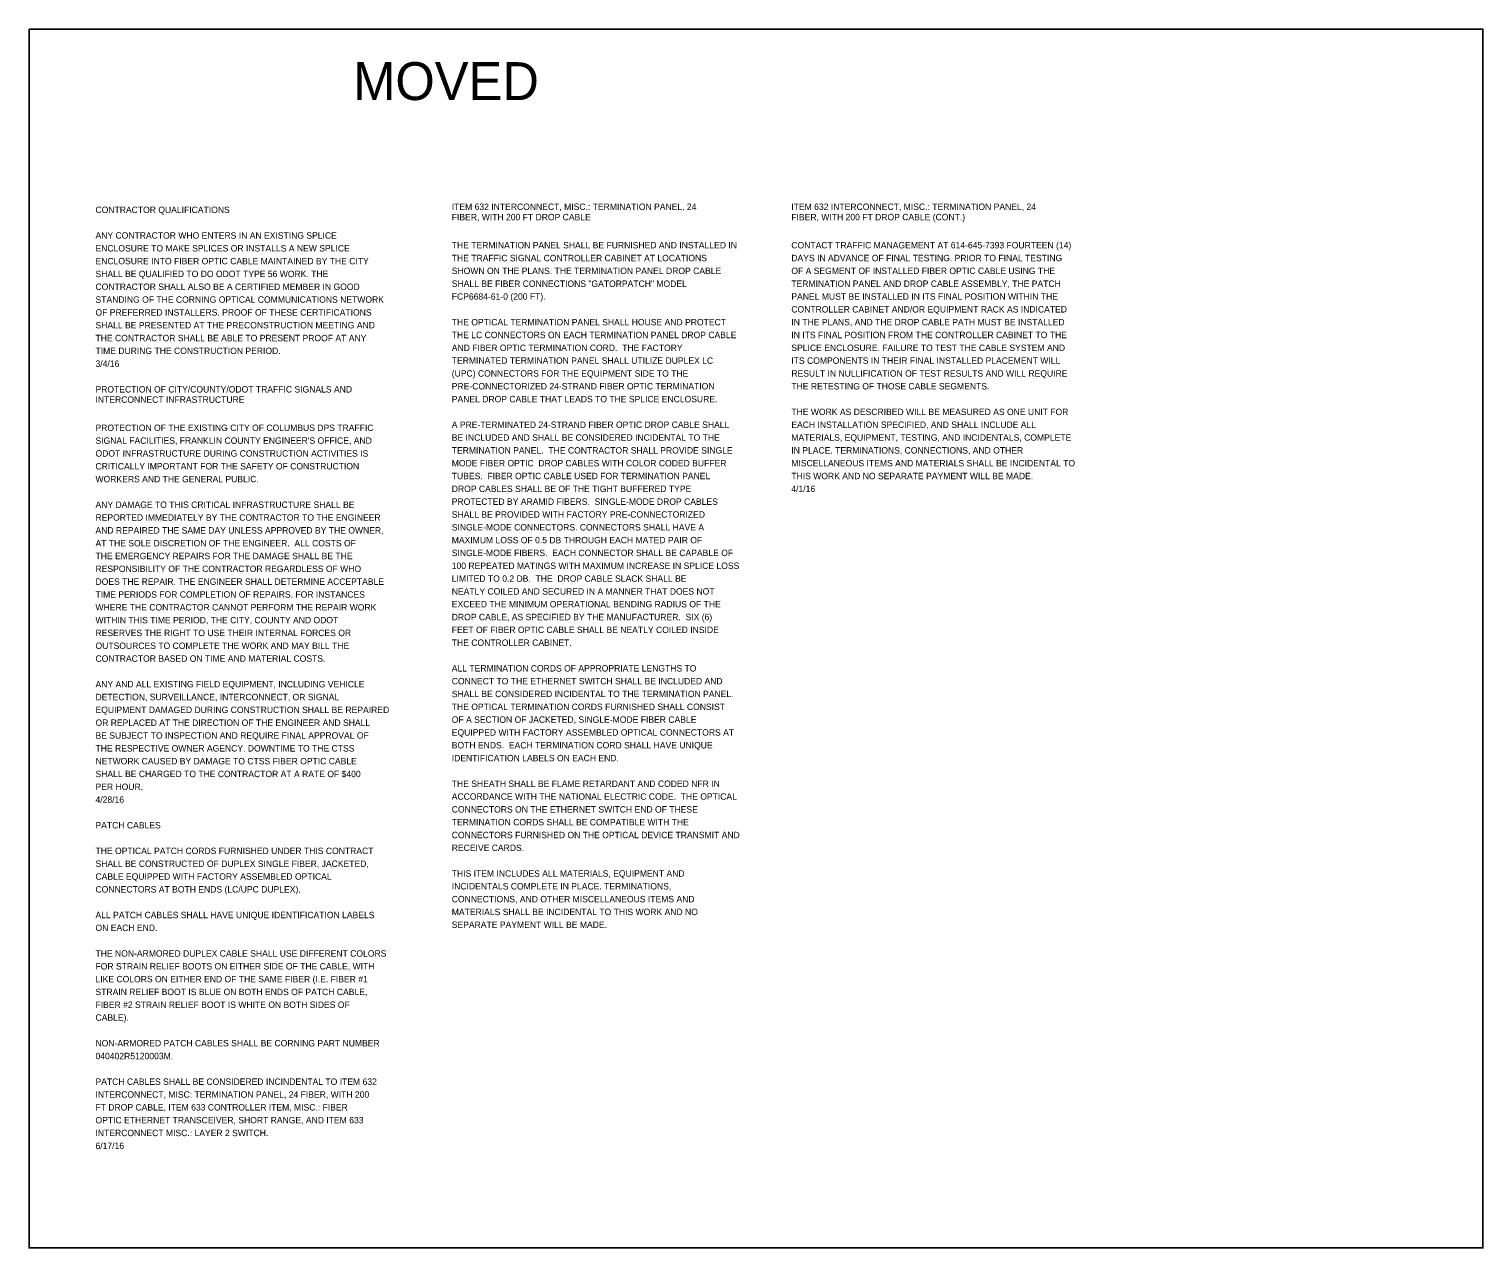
# Model space of a CAD drawing. Extents: x -38 to 65, y -51 to 25.
# Drawn here: x -38.27 to -6.5, y -10.91 to 15.7 of the extents above; entities that cross this region are included whole.
import ezdxf

# ---------------------------------------------------------------- set-up
doc = ezdxf.new("R2010")
doc.units = 0
doc.layers.add('SH_Data', color=7, linetype='Continuous')
doc.layers.add('SH_Text', color=7, linetype='Continuous')

msp = doc.modelspace()

# ---------------------------------------------------------------- linework, layer by layer
at = {"layer": 'SH_Text'}
msp.add_lwpolyline([(-38.266, 15.704), (-6.498, 15.704), (-6.498, -10.913), (-38.266, -10.913)], close=True, dxfattribs=at)

# ---------------------------------------------------------------- texts
at = {"layer": 'SH_Data'}
for s, height, p in [('MOVED', 0.8279, (-31.185, 14.154)), ('CONTRACTOR QUALIFICATIONS', 0.14, (-36.815, 11.687)), ('ITEM 632 INTERCONNECT, MISC.: TERMINATION PANEL, 24 ', 0.14, (-29.03, 11.754)), ('ITEM 632 INTERCONNECT, MISC.: TERMINATION PANEL, 24 ', 0.14, (-21.61, 11.754)), ('FIBER, WITH 200 FT DROP CABLE', 0.14, (-29.03, 11.529)), ('FIBER, WITH 200 FT DROP CABLE (CONT.)', 0.14, (-21.61, 11.529)), ('PROTECTION OF CITY/COUNTY/ODOT TRAFFIC SIGNALS AND ', 0.14, (-36.815, 7.767)), ('INTERCONNECT INFRASTRUCTURE', 0.14, (-36.815, 7.542)), ('PATCH CABLES', 0.14, (-36.815, -1.753))]:
    msp.add_text(s, height=height, dxfattribs=at).set_placement(p)
at = {"layer": 'SH_Text'}
for s, p in [('ANY CONTRACTOR WHO ENTERS IN AN EXISTING SPLICE  ', (-36.815, 11.127)), ('ENCLOSURE TO MAKE SPLICES OR INSTALLS A NEW SPLICE ', (-36.815, 10.847)), ('THE TERMINATION PANEL SHALL BE FURNISHED AND INSTALLED IN ', (-29.03, 10.914)), ('CONTACT TRAFFIC MANAGEMENT AT 614-645-7393 FOURTEEN (14) ', (-21.61, 10.914)), ('ENCLOSURE INTO FIBER OPTIC CABLE MAINTAINED BY THE CITY ', (-36.815, 10.567)), ('THE TRAFFIC SIGNAL CONTROLLER CABINET AT LOCATIONS ', (-29.03, 10.634)), ('SHOWN ON THE PLANS. THE TERMINATION PANEL DROP CABLE ', (-29.03, 10.354)), ('OF A SEGMENT OF INSTALLED FIBER OPTIC CABLE USING THE ', (-21.61, 10.354)), ('DAYS IN ADVANCE OF FINAL TESTING. PRIOR TO FINAL TESTING ', (-21.61, 10.634)), ('SHALL BE QUALIFIED TO DO ODOT TYPE 56 WORK. THE ', (-36.815, 10.287)), ('SHALL BE FIBER CONNECTIONS "GATORPATCH" MODEL ', (-29.03, 10.074)), ('TERMINATION PANEL AND DROP CABLE ASSEMBLY, THE PATCH ', (-21.61, 10.074)), ('STANDING OF THE CORNING OPTICAL COMMUNICATIONS NETWORK ', (-36.815, 9.727)), ('CONTRACTOR SHALL ALSO BE A CERTIFIED MEMBER IN GOOD ', (-36.815, 10.007)), ('FCP6684-61-0 (200 FT).', (-29.03, 9.794)), ('PANEL MUST BE INSTALLED IN ITS FINAL POSITION WITHIN THE ', (-21.61, 9.794)), ('OF PREFERRED INSTALLERS. PROOF OF THESE CERTIFICATIONS ', (-36.815, 9.447)), ('CONTROLLER CABINET AND/OR EQUIPMENT RACK AS INDICATED ', (-21.61, 9.514)), ('SHALL BE PRESENTED AT THE PRECONSTRUCTION MEETING AND ', (-36.815, 9.167)), ('THE OPTICAL TERMINATION PANEL SHALL HOUSE AND PROTECT ', (-29.03, 9.234)), ('IN THE PLANS, AND THE DROP CABLE PATH MUST BE INSTALLED ', (-21.61, 9.234)), ('THE CONTRACTOR SHALL BE ABLE TO PRESENT PROOF AT ANY ', (-36.815, 8.887)), ('THE LC CONNECTORS ON EACH TERMINATION PANEL DROP CABLE ', (-29.03, 8.954)), ('IN ITS FINAL POSITION FROM THE CONTROLLER CABINET TO THE ', (-21.61, 8.954)), ('TIME DURING THE CONSTRUCTION PERIOD.  ', (-36.815, 8.607)), ('AND FIBER OPTIC TERMINATION CORD.  THE FACTORY ', (-29.03, 8.674)), ('SPLICE ENCLOSURE. FAILURE TO TEST THE CABLE SYSTEM AND ', (-21.61, 8.674)), ('3/4/16', (-36.815, 8.327)), ('TERMINATED TERMINATION PANEL SHALL UTILIZE DUPLEX LC ', (-29.03, 8.394)), ('(UPC) CONNECTORS FOR THE EQUIPMENT SIDE TO THE ', (-29.03, 8.114)), ('ITS COMPONENTS IN THEIR FINAL INSTALLED PLACEMENT WILL ', (-21.61, 8.394)), ('PRE-CONNECTORIZED 24-STRAND FIBER OPTIC TERMINATION ', (-29.03, 7.834)), ('THE RETESTING OF THOSE CABLE SEGMENTS.                                       ', (-21.61, 7.834)), ('RESULT IN NULLIFICATION OF TEST RESULTS AND WILL REQUIRE ', (-21.61, 8.114)), ('PANEL DROP CABLE THAT LEADS TO THE SPLICE ENCLOSURE.', (-29.03, 7.554)), ('THE WORK AS DESCRIBED WILL BE MEASURED AS ONE UNIT FOR ', (-21.61, 7.274)), ('PROTECTION OF THE EXISTING CITY OF COLUMBUS DPS TRAFFIC ', (-36.815, 6.927)), ('A PRE-TERMINATED 24-STRAND FIBER OPTIC DROP CABLE SHALL ', (-29.03, 6.994)), ('EACH INSTALLATION SPECIFIED, AND SHALL INCLUDE ALL ', (-21.61, 6.994)), ("SIGNAL FACILITIES, FRANKLIN COUNTY ENGINEER'S OFFICE, AND ", (-36.815, 6.647)), ('BE INCLUDED AND SHALL BE CONSIDERED INCIDENTAL TO THE ', (-29.03, 6.714)), ('MATERIALS, EQUIPMENT, TESTING, AND INCIDENTALS, COMPLETE ', (-21.61, 6.714)), ('ODOT INFRASTRUCTURE DURING CONSTRUCTION ACTIVITIES IS ', (-36.815, 6.367)), ('TERMINATION PANEL.  THE CONTRACTOR SHALL PROVIDE SINGLE ', (-29.03, 6.434)), ('IN PLACE. TERMINATIONS, CONNECTIONS, AND OTHER ', (-21.61, 6.434)), ('CRITICALLY IMPORTANT FOR THE SAFETY OF CONSTRUCTION ', (-36.815, 6.087)), ('MODE FIBER OPTIC  DROP CABLES WITH COLOR CODED BUFFER ', (-29.03, 6.154)), ('MISCELLANEOUS ITEMS AND MATERIALS SHALL BE INCIDENTAL TO ', (-21.61, 6.154)), ('WORKERS AND THE GENERAL PUBLIC. ', (-36.815, 5.807)), ('TUBES.  FIBER OPTIC CABLE USED FOR TERMINATION PANEL ', (-29.03, 5.874)), ('DROP CABLES SHALL BE OF THE TIGHT BUFFERED TYPE ', (-29.03, 5.594)), ('THIS WORK AND NO SEPARATE PAYMENT WILL BE MADE. ', (-21.61, 5.874)), ('4/1/16', (-21.61, 5.594)), ('PROTECTED BY ARAMID FIBERS.  SINGLE-MODE DROP CABLES ', (-29.03, 5.314)), ('ANY DAMAGE TO THIS CRITICAL INFRASTRUCTURE SHALL BE ', (-36.815, 5.247)), ('REPORTED IMMEDIATELY BY THE CONTRACTOR TO THE ENGINEER ', (-36.815, 4.967)), ('SHALL BE PROVIDED WITH FACTORY PRE-CONNECTORIZED ', (-29.03, 5.034)), ('AND REPAIRED THE SAME DAY UNLESS APPROVED BY THE OWNER, ', (-36.815, 4.687)), ('SINGLE-MODE CONNECTORS. CONNECTORS SHALL HAVE A ', (-29.03, 4.754)), ('AT THE SOLE DISCRETION OF THE ENGINEER.  ALL COSTS OF ', (-36.815, 4.407)), ('MAXIMUM LOSS OF 0.5 DB THROUGH EACH MATED PAIR OF ', (-29.03, 4.474)), ('THE EMERGENCY REPAIRS FOR THE DAMAGE SHALL BE THE ', (-36.815, 4.127)), ('SINGLE-MODE FIBERS.  EACH CONNECTOR SHALL BE CAPABLE OF ', (-29.03, 4.194)), ('RESPONSIBILITY OF THE CONTRACTOR REGARDLESS OF WHO ', (-36.815, 3.847)), ('100 REPEATED MATINGS WITH MAXIMUM INCREASE IN SPLICE LOSS ', (-29.03, 3.914)), ('DOES THE REPAIR. THE ENGINEER SHALL DETERMINE ACCEPTABLE ', (-36.815, 3.567)), ('LIMITED TO 0.2 DB.  THE  DROP CABLE SLACK SHALL BE ', (-29.03, 3.634)), ('NEATLY COILED AND SECURED IN A MANNER THAT DOES NOT ', (-29.03, 3.354)), ('TIME PERIODS FOR COMPLETION OF REPAIRS. FOR INSTANCES ', (-36.815, 3.287)), ('EXCEED THE MINIMUM OPERATIONAL BENDING RADIUS OF THE ', (-29.03, 3.074)), ('WHERE THE CONTRACTOR CANNOT PERFORM THE REPAIR WORK ', (-36.815, 3.007)), ('WITHIN THIS TIME PERIOD, THE CITY, COUNTY AND ODOT ', (-36.815, 2.727)), ('DROP CABLE, AS SPECIFIED BY THE MANUFACTURER.  SIX (6) ', (-29.03, 2.794)), ('RESERVES THE RIGHT TO USE THEIR INTERNAL FORCES OR ', (-36.815, 2.447)), ('FEET OF FIBER OPTIC CABLE SHALL BE NEATLY COILED INSIDE ', (-29.03, 2.514)), ('OUTSOURCES TO COMPLETE THE WORK AND MAY BILL THE ', (-36.815, 2.167)), ('THE CONTROLLER CABINET.', (-29.03, 2.234)), ('CONTRACTOR BASED ON TIME AND MATERIAL COSTS. ', (-36.815, 1.887)), ('ALL TERMINATION CORDS OF APPROPRIATE LENGTHS TO ', (-29.03, 1.674)), ('ANY AND ALL EXISTING FIELD EQUIPMENT, INCLUDING VEHICLE ', (-36.815, 1.327)), ('CONNECT TO THE ETHERNET SWITCH SHALL BE INCLUDED AND ', (-29.03, 1.394)), ('DETECTION, SURVEILLANCE, INTERCONNECT, OR SIGNAL ', (-36.815, 1.047)), ('THE OPTICAL TERMINATION CORDS FURNISHED SHALL CONSIST ', (-29.03, 0.834)), ('SHALL BE CONSIDERED INCIDENTAL TO THE TERMINATION PANEL.  ', (-29.03, 1.114)), ('EQUIPMENT DAMAGED DURING CONSTRUCTION SHALL BE REPAIRED ', (-36.815, 0.767)), ('OF A SECTION OF JACKETED, SINGLE-MODE FIBER CABLE ', (-29.03, 0.554)), ('OR REPLACED AT THE DIRECTION OF THE ENGINEER AND SHALL ', (-36.815, 0.487)), ('BE SUBJECT TO INSPECTION AND REQUIRE FINAL APPROVAL OF ', (-36.815, 0.207)), ('EQUIPPED WITH FACTORY ASSEMBLED OPTICAL CONNECTORS AT ', (-29.03, 0.274)), ('THE RESPECTIVE OWNER AGENCY. DOWNTIME TO THE CTSS ', (-36.815, -0.073)), ('BOTH ENDS.  EACH TERMINATION CORD SHALL HAVE UNIQUE ', (-29.03, -0.006)), ('NETWORK CAUSED BY DAMAGE TO CTSS FIBER OPTIC CABLE ', (-36.815, -0.353)), ('IDENTIFICATION LABELS ON EACH END.', (-29.03, -0.286)), ('SHALL BE CHARGED TO THE CONTRACTOR AT A RATE OF $400 ', (-36.815, -0.633)), ('PER HOUR.', (-36.815, -0.913)), ('THE SHEATH SHALL BE FLAME RETARDANT AND CODED NFR IN ', (-29.03, -0.846)), ('4/28/16', (-36.815, -1.193)), ('ACCORDANCE WITH THE NATIONAL ELECTRIC CODE.  THE OPTICAL ', (-29.03, -1.126)), ('CONNECTORS ON THE ETHERNET SWITCH END OF THESE ', (-29.03, -1.406)), ('TERMINATION CORDS SHALL BE COMPATIBLE WITH THE ', (-29.03, -1.686)), ('CONNECTORS FURNISHED ON THE OPTICAL DEVICE TRANSMIT AND ', (-29.03, -1.966)), ('THE OPTICAL PATCH CORDS FURNISHED UNDER THIS CONTRACT ', (-36.815, -2.313)), ('RECEIVE CARDS.', (-29.03, -2.246)), ('SHALL BE CONSTRUCTED OF DUPLEX SINGLE FIBER, JACKETED, ', (-36.815, -2.593)), ('CABLE EQUIPPED WITH FACTORY ASSEMBLED OPTICAL ', (-36.815, -2.873)), ('THIS ITEM INCLUDES ALL MATERIALS, EQUIPMENT AND ', (-29.03, -2.806)), ('CONNECTORS AT BOTH ENDS (LC/UPC DUPLEX).  ', (-36.815, -3.153)), ('INCIDENTALS COMPLETE IN PLACE. TERMINATIONS, ', (-29.03, -3.086)), ('CONNECTIONS, AND OTHER MISCELLANEOUS ITEMS AND ', (-29.03, -3.366)), ('ALL PATCH CABLES SHALL HAVE UNIQUE IDENTIFICATION LABELS ', (-36.815, -3.713)), ('SEPARATE PAYMENT WILL BE MADE.', (-29.03, -3.926)), ('MATERIALS SHALL BE INCIDENTAL TO THIS WORK AND NO ', (-29.03, -3.646)), ('ON EACH END.', (-36.815, -3.993)), ('THE NON-ARMORED DUPLEX CABLE SHALL USE DIFFERENT COLORS ', (-36.815, -4.553)), ('FOR STRAIN RELIEF BOOTS ON EITHER SIDE OF THE CABLE, WITH ', (-36.815, -4.833)), ('LIKE COLORS ON EITHER END OF THE SAME FIBER (I.E. FIBER #1 ', (-36.815, -5.113)), ('STRAIN RELIEF BOOT IS BLUE ON BOTH ENDS OF PATCH CABLE, ', (-36.815, -5.393)), ('FIBER #2 STRAIN RELIEF BOOT IS WHITE ON BOTH SIDES OF ', (-36.815, -5.673)), ('CABLE). ', (-36.815, -5.953)), ('040402R5120003M.', (-36.815, -6.793)), ('NON-ARMORED PATCH CABLES SHALL BE CORNING PART NUMBER ', (-36.815, -6.513)), ('PATCH CABLES SHALL BE CONSIDERED INCINDENTAL TO ITEM 632 ', (-36.815, -7.353)), ('INTERCONNECT, MISC: TERMINATION PANEL, 24 FIBER, WITH 200 ', (-36.815, -7.633)), ('FT DROP CABLE, ITEM 633 CONTROLLER ITEM, MISC.: FIBER ', (-36.815, -7.913)), ('OPTIC ETHERNET TRANSCEIVER, SHORT RANGE, AND ITEM 633 ', (-36.815, -8.193)), ('INTERCONNECT MISC.: LAYER 2 SWITCH. ', (-36.815, -8.473)), ('6/17/16', (-36.815, -8.753))]:
    msp.add_text(s, height=0.14, dxfattribs=at).set_placement(p)

doc.saveas('drawing.dxf')
